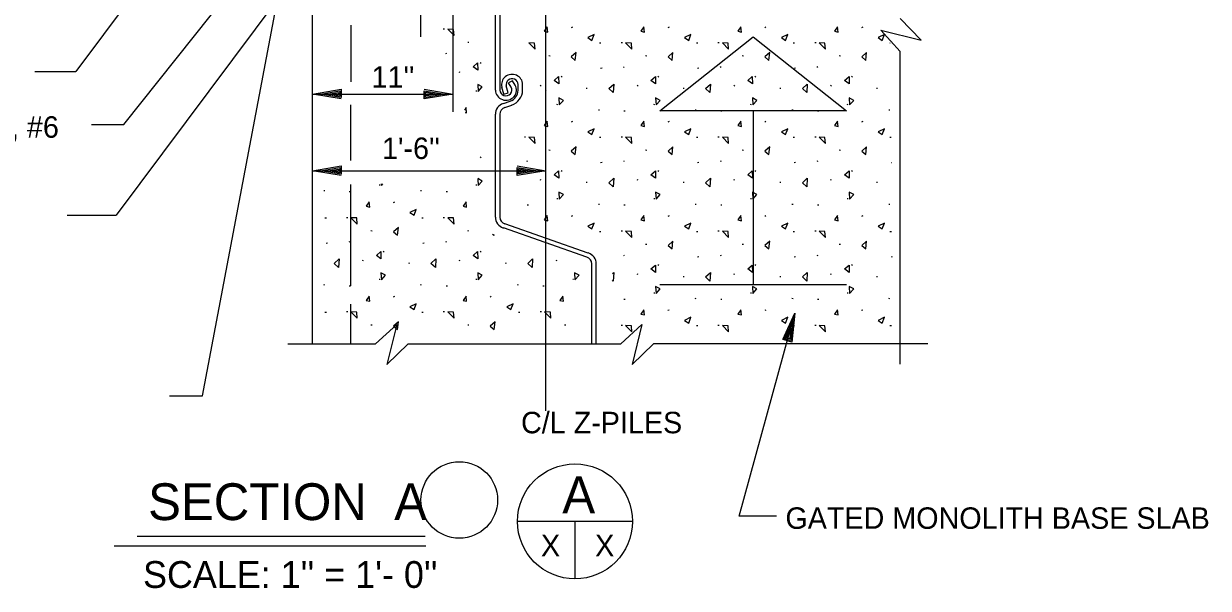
# Model space of a CAD drawing. Extents: x 22369.6 to 22428.3, y 22369.6 to 22415.
# Drawn here: x 22399.65 to 22409.95, y 22392.13 to 22397.04 of the extents above; entities that cross this region are included whole.
import ezdxf

# ---------------------------------------------------------------- set-up
doc = ezdxf.new("R2010")
doc.units = 0
for name, color, linetype in [('Level 1', 7, 'Continuous'), ('Level 10', 7, 'Continuous'), ('Level 2', 7, 'Continuous'), ('Level 3', 7, 'Continuous'), ('Level 4', 7, 'Continuous'), ('Level 44', 7, 'Continuous'), ('Level 7', 7, 'Continuous')]:
    doc.layers.add(name, color=color, linetype=linetype)

msp = doc.modelspace()

# ---------------------------------------------------------------- linework, layer by layer
at = {"layer": 'Level 1'}
for p, q in [((22403.103, 22396.931), (22403.103, 22400.124)), ((22404.188, 22393.677), (22404.188, 22399.363)), ((22403.381, 22399.057), (22403.381, 22396.277)), ((22402.977, 22398.76), (22400.451, 22395.38)), ((22401.272, 22398.196), (22400.102, 22396.63)), ((22407.451, 22396.902), (22407.27, 22397.089)), ((22407.27, 22396.804), (22407.102, 22396.988)), ((22407.102, 22396.988), (22407.451, 22396.902)), ((22407.27, 22394.082), (22407.27, 22396.804)), ((22399.745, 22396.63), (22400.102, 22396.63)), ((22402.159, 22396.432), (22403.381, 22396.432)), ((22404.19, 22396.466), (22404.19, 22396.466)), ((22404.194, 22396.466), (22404.194, 22396.466)), ((22402.159, 22395.766), (22404.188, 22395.766)), ((22400.025, 22395.38), (22400.451, 22395.38)), ((22402.708, 22394.26), (22402.892, 22394.429)), ((22402.892, 22394.429), (22402.806, 22394.079)), ((22404.84, 22394.26), (22405.024, 22394.429)), ((22405.024, 22394.429), (22404.938, 22394.079)), ((22401.945, 22394.26), (22402.708, 22394.26)), ((22402.806, 22394.079), (22402.992, 22394.26)), ((22402.992, 22394.26), (22404.84, 22394.26)), ((22404.938, 22394.079), (22405.125, 22394.26)), ((22407.51, 22394.26), (22405.125, 22394.26))]:
    msp.add_line(p, q, dxfattribs=at)
for points in [[(22400.916, 22393.807), (22401.203, 22393.807), (22402.11, 22398.602)], [(22400.238, 22396.169), (22400.519, 22396.169), (22401.736, 22397.698)], [(22406.194, 22392.76), (22405.871, 22392.76), (22406.355, 22394.528)]]:
    msp.add_lwpolyline(points, dxfattribs=at)
at = {"layer": 'Level 10'}
for p, q in [((22402.492, 22397.032), (22402.492, 22396.538)), ((22402.492, 22395.855), (22402.492, 22396.338)), ((22406.803, 22396.286), (22405.181, 22396.286)), ((22405.992, 22396.286), (22405.992, 22394.772)), ((22402.492, 22394.766), (22402.492, 22395.645)), ((22406.803, 22394.772), (22405.181, 22394.772)), ((22402.492, 22394.26), (22402.492, 22394.604)), ((22400.634, 22392.586), (22403.138, 22392.586)), ((22400.434, 22392.503), (22403.144, 22392.503))]:
    msp.add_line(p, q, dxfattribs=at)
msp.add_lwpolyline([(22405.181, 22396.286), (22405.992, 22396.931), (22406.803, 22396.286)], close=True, dxfattribs=at)
at = {"layer": 'Level 2'}
for p, q in [((22403.751, 22396.467), (22403.751, 22397.362)), ((22403.79, 22396.467), (22403.79, 22397.362)), ((22403.899, 22396.549), (22403.865, 22396.53)), ((22403.922, 22396.511), (22403.899, 22396.549)), ((22402.159, 22396.432), (22402.159, 22396.432)), ((22402.228, 22396.432), (22402.228, 22396.432)), ((22403.311, 22396.432), (22403.311, 22396.432)), ((22403.381, 22396.432), (22403.381, 22396.432)), ((22403.823, 22396.433), (22403.806, 22396.493)), ((22403.823, 22396.433), (22403.861, 22396.442)), ((22403.861, 22396.442), (22403.844, 22396.503)), ((22403.888, 22396.492), (22403.865, 22396.53)), ((22403.947, 22396.466), (22403.947, 22396.516)), ((22403.986, 22396.466), (22403.986, 22396.516)), ((22404.188, 22396.467), (22404.188, 22396.467)), ((22403.82, 22396.351), (22403.878, 22396.372)), ((22403.833, 22396.316), (22403.892, 22396.336)), ((22403.751, 22395.362), (22403.751, 22396.257)), ((22403.79, 22395.362), (22403.79, 22396.257)), ((22402.159, 22395.766), (22402.159, 22395.766)), ((22402.228, 22395.766), (22402.228, 22395.766)), ((22404.119, 22395.766), (22404.119, 22395.766)), ((22404.188, 22395.766), (22404.188, 22395.766)), ((22404.558, 22395.05), (22403.833, 22395.303)), ((22404.545, 22395.015), (22403.82, 22395.268)), ((22404.588, 22394.26), (22404.588, 22394.956)), ((22404.627, 22394.26), (22404.627, 22394.956)), ((22406.355, 22394.528), (22406.355, 22394.528)), ((22406.337, 22394.461), (22406.337, 22394.461))]:
    msp.add_line(p, q, dxfattribs=at)
for points in [[(22402.408, 22396.391), (22402.159, 22396.432), (22402.408, 22396.474), (22402.408, 22396.403), (22402.228, 22396.432), (22402.397, 22396.46), (22402.397, 22396.415), (22402.295, 22396.432), (22402.387, 22396.447), (22402.387, 22396.428), (22402.364, 22396.432)], [(22403.131, 22396.474), (22403.381, 22396.432), (22403.131, 22396.391), (22403.131, 22396.462), (22403.311, 22396.432), (22403.142, 22396.404), (22403.142, 22396.45), (22403.245, 22396.432), (22403.153, 22396.418), (22403.153, 22396.436), (22403.175, 22396.432)], [(22402.408, 22395.724), (22402.159, 22395.766), (22402.408, 22395.807), (22402.408, 22395.736), (22402.228, 22395.766), (22402.397, 22395.794), (22402.397, 22395.748), (22402.295, 22395.766), (22402.387, 22395.78), (22402.387, 22395.762), (22402.364, 22395.766)], [(22403.939, 22395.807), (22404.188, 22395.766), (22403.939, 22395.724), (22403.939, 22395.795), (22404.119, 22395.766), (22403.95, 22395.738), (22403.95, 22395.783), (22404.052, 22395.766), (22403.96, 22395.751), (22403.96, 22395.77), (22403.983, 22395.766)], [(22406.25, 22394.298), (22406.355, 22394.528), (22406.329, 22394.276), (22406.261, 22394.295), (22406.337, 22394.461), (22406.319, 22394.29), (22406.276, 22394.302), (22406.319, 22394.396), (22406.309, 22394.304), (22406.291, 22394.309), (22406.301, 22394.33)]]:
    msp.add_lwpolyline(points, dxfattribs=at)
for centre, major_axis, start_param, end_param in [((22403.895, 22396.516), (0.0916, 0), 0, 3.403392), ((22403.895, 22396.516), (0.0523, 0), 0, 3.403392), ((22403.842, 22396.467), (-0.0916, 0), 0, 3.665191), ((22403.842, 22396.467), (-0.0523, 0), 0, 3.665191), ((22403.842, 22396.466), (0.105, 0), 5.061528, 6.283185), ((22403.842, 22396.466), (0.144, 0), 5.061528, 6.283185), ((22403.855, 22396.257), (0.105, 0), 1.919936, 3.141593), ((22403.855, 22396.257), (0.0654, 0), 1.919936, 3.141593), ((22403.855, 22395.362), (0.105, 0), 3.141593, 4.363142), ((22403.855, 22395.362), (0.0654, 0), 3.141593, 4.363142), ((22404.522, 22394.956), (0.0654, 0), 0, 1.22155), ((22404.522, 22394.956), (0.105, 0), 0, 1.22155)]:
    msp.add_ellipse(centre, major_axis=major_axis, ratio=0.957796, start_param=start_param, end_param=end_param, dxfattribs=at)
at = {"layer": 'Level 3'}
for centre, radius in [((22403.436, 22392.902), 0.333), ((22404.442, 22392.716), 0.5)]:
    msp.add_circle(centre, radius, dxfattribs=at)
at = {"layer": 'Level 4'}
msp.add_line((22404.19, 22394.06), (22404.19, 22394.06), dxfattribs=at)
at = {"layer": 'Level 44'}
for p, q in [((22403.308, 22396.997), (22403.297, 22396.997)), ((22404.419, 22397.013), (22404.409, 22397.008)), ((22405.26, 22397.013), (22405.25, 22397.008)), ((22406.102, 22397.013), (22406.092, 22397.008)), ((22406.944, 22397.013), (22406.934, 22397.008)), ((22403.52, 22396.88), (22403.509, 22396.882)), ((22404.668, 22396.875), (22404.656, 22396.875)), ((22404.854, 22396.879), (22404.844, 22396.879)), ((22405.509, 22396.875), (22405.498, 22396.875)), ((22405.696, 22396.879), (22405.685, 22396.879)), ((22406.351, 22396.875), (22406.34, 22396.875)), ((22406.538, 22396.879), (22406.527, 22396.879)), ((22407.184, 22396.875), (22407.181, 22396.875)), ((22403.324, 22396.786), (22403.316, 22396.783)), ((22404.225, 22396.763), (22404.214, 22396.764)), ((22405.066, 22396.763), (22405.056, 22396.764)), ((22405.908, 22396.763), (22405.897, 22396.764)), ((22406.75, 22396.763), (22406.739, 22396.764)), ((22403.626, 22396.698), (22403.617, 22396.703)), ((22404.677, 22396.657), (22404.665, 22396.654)), ((22404.871, 22396.668), (22404.863, 22396.665)), ((22405.518, 22396.657), (22405.507, 22396.654)), ((22405.712, 22396.668), (22405.704, 22396.665)), ((22406.36, 22396.657), (22406.349, 22396.654)), ((22406.554, 22396.668), (22406.546, 22396.665)), ((22403.445, 22396.62), (22403.436, 22396.624)), ((22404.331, 22396.58), (22404.321, 22396.585)), ((22405.172, 22396.58), (22405.163, 22396.585)), ((22406.014, 22396.58), (22406.005, 22396.585)), ((22406.856, 22396.58), (22406.846, 22396.585)), ((22403.589, 22396.458), (22403.58, 22396.459)), ((22404.149, 22396.502), (22404.14, 22396.506)), ((22404.549, 22396.482), (22404.54, 22396.481)), ((22404.991, 22396.502), (22404.982, 22396.506)), ((22405.391, 22396.482), (22405.382, 22396.481)), ((22405.833, 22396.502), (22405.824, 22396.506)), ((22406.232, 22396.482), (22406.223, 22396.481)), ((22406.674, 22396.502), (22406.665, 22396.506)), ((22407.074, 22396.482), (22407.065, 22396.481)), ((22404.293, 22396.34), (22404.285, 22396.341)), ((22405.135, 22396.34), (22405.127, 22396.341)), ((22405.977, 22396.34), (22405.968, 22396.341)), ((22406.818, 22396.34), (22406.81, 22396.341)), ((22404.654, 22396.292), (22404.646, 22396.293)), ((22404.879, 22396.285), (22404.867, 22396.285)), ((22405.496, 22396.292), (22405.488, 22396.293)), ((22405.72, 22396.285), (22405.709, 22396.285)), ((22406.338, 22396.292), (22406.329, 22396.293)), ((22406.562, 22396.285), (22406.551, 22396.285)), ((22407.179, 22396.292), (22407.171, 22396.293)), ((22404.419, 22396.194), (22404.409, 22396.189)), ((22405.26, 22396.194), (22405.25, 22396.189)), ((22406.102, 22396.194), (22406.092, 22396.189)), ((22406.944, 22396.194), (22406.934, 22396.189)), ((22404.013, 22396.059), (22404.003, 22396.059)), ((22404.668, 22396.055), (22404.656, 22396.055)), ((22404.854, 22396.059), (22404.844, 22396.059)), ((22405.509, 22396.055), (22405.498, 22396.055)), ((22405.696, 22396.059), (22405.685, 22396.059)), ((22406.351, 22396.055), (22406.34, 22396.055)), ((22406.538, 22396.059), (22406.527, 22396.059)), ((22407.191, 22396.055), (22407.181, 22396.055)), ((22404.225, 22395.943), (22404.214, 22395.945)), ((22405.066, 22395.943), (22405.056, 22395.945)), ((22405.908, 22395.943), (22405.897, 22395.945)), ((22406.75, 22395.943), (22406.739, 22395.945)), ((22403.626, 22395.878), (22403.617, 22395.884)), ((22404.029, 22395.848), (22404.021, 22395.845)), ((22404.677, 22395.837), (22404.665, 22395.834)), ((22404.871, 22395.848), (22404.863, 22395.845)), ((22405.518, 22395.837), (22405.507, 22395.834)), ((22405.712, 22395.848), (22405.704, 22395.845)), ((22406.36, 22395.837), (22406.349, 22395.834)), ((22406.554, 22395.848), (22406.546, 22395.845)), ((22407.193, 22395.835), (22407.19, 22395.834)), ((22404.331, 22395.76), (22404.321, 22395.766)), ((22405.172, 22395.76), (22405.163, 22395.766)), ((22406.014, 22395.76), (22406.005, 22395.766)), ((22406.856, 22395.76), (22406.846, 22395.766)), ((22402.747, 22395.639), (22402.739, 22395.639)), ((22403.589, 22395.639), (22403.58, 22395.639)), ((22404.149, 22395.683), (22404.14, 22395.687)), ((22404.549, 22395.663), (22404.54, 22395.662)), ((22404.991, 22395.683), (22404.982, 22395.687)), ((22405.391, 22395.663), (22405.382, 22395.662)), ((22405.833, 22395.683), (22405.824, 22395.687)), ((22406.232, 22395.663), (22406.223, 22395.662)), ((22406.674, 22395.683), (22406.665, 22395.687)), ((22407.074, 22395.663), (22407.065, 22395.662)), ((22402.266, 22395.59), (22402.258, 22395.591)), ((22402.49, 22395.583), (22402.479, 22395.583)), ((22403.108, 22395.59), (22403.1, 22395.591)), ((22403.332, 22395.583), (22403.321, 22395.583)), ((22404.293, 22395.521), (22404.285, 22395.521)), ((22405.135, 22395.521), (22405.127, 22395.521)), ((22405.977, 22395.521), (22405.968, 22395.521)), ((22406.818, 22395.521), (22406.81, 22395.521)), ((22402.872, 22395.492), (22402.862, 22395.487)), ((22404.037, 22395.465), (22404.026, 22395.465)), ((22404.654, 22395.472), (22404.646, 22395.473)), ((22404.879, 22395.465), (22404.867, 22395.465)), ((22405.496, 22395.472), (22405.488, 22395.473)), ((22405.72, 22395.465), (22405.709, 22395.465)), ((22406.338, 22395.472), (22406.329, 22395.473)), ((22406.562, 22395.465), (22406.551, 22395.465)), ((22407.179, 22395.472), (22407.171, 22395.473)), ((22402.28, 22395.353), (22402.268, 22395.353)), ((22402.466, 22395.357), (22402.456, 22395.357)), ((22403.121, 22395.353), (22403.11, 22395.353)), ((22403.308, 22395.357), (22403.297, 22395.357)), ((22404.419, 22395.374), (22404.409, 22395.369)), ((22405.26, 22395.374), (22405.25, 22395.369)), ((22406.102, 22395.374), (22406.092, 22395.369)), ((22406.944, 22395.374), (22406.934, 22395.369)), ((22402.678, 22395.241), (22402.668, 22395.243)), ((22403.52, 22395.241), (22403.509, 22395.243)), ((22404.668, 22395.235), (22404.656, 22395.235)), ((22404.854, 22395.239), (22404.844, 22395.239)), ((22405.509, 22395.235), (22405.498, 22395.235)), ((22405.696, 22395.239), (22405.685, 22395.239)), ((22406.351, 22395.235), (22406.34, 22395.235)), ((22406.538, 22395.239), (22406.527, 22395.239)), ((22407.193, 22395.235), (22407.181, 22395.235)), ((22402.289, 22395.135), (22402.277, 22395.132)), ((22402.483, 22395.147), (22402.475, 22395.143)), ((22403.13, 22395.135), (22403.119, 22395.132)), ((22403.324, 22395.147), (22403.316, 22395.143)), ((22405.066, 22395.123), (22405.056, 22395.125)), ((22405.908, 22395.123), (22405.897, 22395.125)), ((22406.75, 22395.123), (22406.739, 22395.125)), ((22402.784, 22395.058), (22402.775, 22395.064)), ((22403.626, 22395.058), (22403.617, 22395.064)), ((22404.871, 22395.029), (22404.863, 22395.025)), ((22405.518, 22395.017), (22405.507, 22395.014)), ((22405.712, 22395.029), (22405.704, 22395.025)), ((22406.36, 22395.017), (22406.349, 22395.014)), ((22406.554, 22395.029), (22406.546, 22395.025)), ((22407.2, 22395.017), (22407.19, 22395.014)), ((22402.603, 22394.981), (22402.594, 22394.985)), ((22403.003, 22394.961), (22402.994, 22394.96)), ((22403.445, 22394.981), (22403.436, 22394.985)), ((22403.844, 22394.961), (22403.835, 22394.96)), ((22404.286, 22394.981), (22404.277, 22394.985)), ((22405.172, 22394.94), (22405.163, 22394.946)), ((22406.014, 22394.94), (22406.005, 22394.946)), ((22406.856, 22394.94), (22406.846, 22394.946)), ((22402.747, 22394.819), (22402.739, 22394.819)), ((22403.589, 22394.819), (22403.58, 22394.819)), ((22404.43, 22394.819), (22404.422, 22394.819)), ((22404.991, 22394.863), (22404.982, 22394.867)), ((22405.391, 22394.843), (22405.382, 22394.842)), ((22405.833, 22394.863), (22405.824, 22394.867)), ((22406.232, 22394.843), (22406.223, 22394.842)), ((22406.674, 22394.863), (22406.665, 22394.867)), ((22407.074, 22394.843), (22407.065, 22394.842)), ((22402.266, 22394.77), (22402.258, 22394.772)), ((22402.49, 22394.763), (22402.479, 22394.763)), ((22403.108, 22394.77), (22403.1, 22394.772)), ((22403.332, 22394.763), (22403.321, 22394.763)), ((22403.95, 22394.77), (22403.941, 22394.772)), ((22404.174, 22394.763), (22404.163, 22394.763)), ((22405.135, 22394.701), (22405.127, 22394.701)), ((22405.977, 22394.701), (22405.968, 22394.701)), ((22406.818, 22394.701), (22406.81, 22394.701)), ((22402.872, 22394.672), (22402.862, 22394.667)), ((22403.714, 22394.672), (22403.704, 22394.667)), ((22404.879, 22394.645), (22404.867, 22394.645)), ((22405.496, 22394.652), (22405.488, 22394.654)), ((22405.72, 22394.645), (22405.709, 22394.645)), ((22406.338, 22394.652), (22406.329, 22394.654)), ((22406.562, 22394.645), (22406.551, 22394.645)), ((22407.179, 22394.652), (22407.171, 22394.654)), ((22402.28, 22394.534), (22402.268, 22394.534)), ((22402.466, 22394.538), (22402.456, 22394.538)), ((22403.121, 22394.534), (22403.11, 22394.534)), ((22403.308, 22394.538), (22403.297, 22394.538)), ((22403.963, 22394.534), (22403.952, 22394.534)), ((22404.15, 22394.538), (22404.139, 22394.538)), ((22405.26, 22394.554), (22405.25, 22394.549)), ((22406.102, 22394.554), (22406.092, 22394.549)), ((22406.944, 22394.554), (22406.934, 22394.549)), ((22402.678, 22394.421), (22402.668, 22394.423)), ((22403.52, 22394.421), (22403.509, 22394.423)), ((22404.362, 22394.421), (22404.351, 22394.423)), ((22404.854, 22394.42), (22404.844, 22394.42)), ((22405.509, 22394.416), (22405.498, 22394.416)), ((22405.696, 22394.42), (22405.685, 22394.42)), ((22406.351, 22394.416), (22406.34, 22394.416)), ((22406.538, 22394.42), (22406.527, 22394.42)), ((22407.193, 22394.416), (22407.181, 22394.416))]:
    msp.add_line(p, q, dxfattribs=at)
for points in [[(22403.386, 22396.994), (22403.336, 22396.997), (22403.39, 22396.942)], [(22404.205, 22396.971), (22404.199, 22397.017), (22404.174, 22396.979)], [(22404.589, 22396.899), (22404.609, 22396.95), (22404.554, 22396.924)], [(22405.047, 22396.971), (22405.041, 22397.017), (22405.015, 22396.979)], [(22405.431, 22396.899), (22405.45, 22396.95), (22405.395, 22396.924)], [(22405.889, 22396.971), (22405.883, 22397.017), (22405.857, 22396.979)], [(22406.272, 22396.899), (22406.292, 22396.95), (22406.237, 22396.924)], [(22406.73, 22396.971), (22406.724, 22397.017), (22406.699, 22396.979)], [(22407.114, 22396.899), (22407.134, 22396.95), (22407.079, 22396.924)], [(22404.091, 22396.876), (22404.041, 22396.879), (22404.095, 22396.824)], [(22404.932, 22396.876), (22404.882, 22396.879), (22404.937, 22396.824)], [(22405.774, 22396.876), (22405.724, 22396.879), (22405.778, 22396.824)], [(22406.616, 22396.876), (22406.566, 22396.879), (22406.62, 22396.824)], [(22404.452, 22396.793), (22404.41, 22396.755), (22404.445, 22396.725)], [(22405.294, 22396.793), (22405.251, 22396.755), (22405.287, 22396.725)], [(22406.136, 22396.793), (22406.093, 22396.755), (22406.128, 22396.725)], [(22406.977, 22396.793), (22406.935, 22396.755), (22406.97, 22396.725)], [(22403.596, 22396.639), (22403.556, 22396.669), (22403.595, 22396.703)], [(22404.301, 22396.521), (22404.261, 22396.551), (22404.3, 22396.585)], [(22405.143, 22396.521), (22405.103, 22396.551), (22405.141, 22396.585)], [(22405.985, 22396.521), (22405.945, 22396.551), (22405.983, 22396.585)], [(22406.826, 22396.521), (22406.786, 22396.551), (22406.825, 22396.585)], [(22403.601, 22396.455), (22403.636, 22396.495), (22403.596, 22396.517)], [(22404.774, 22396.446), (22404.736, 22396.481), (22404.779, 22396.519)], [(22405.616, 22396.446), (22405.577, 22396.481), (22405.62, 22396.519)], [(22406.458, 22396.446), (22406.419, 22396.481), (22406.462, 22396.519)], [(22404.305, 22396.338), (22404.341, 22396.378), (22404.301, 22396.399)], [(22405.147, 22396.338), (22405.183, 22396.378), (22405.143, 22396.399)], [(22405.989, 22396.338), (22406.024, 22396.378), (22405.985, 22396.399)], [(22406.83, 22396.338), (22406.866, 22396.378), (22406.826, 22396.399)], [(22404.205, 22396.151), (22404.199, 22396.197), (22404.174, 22396.159)], [(22404.589, 22396.08), (22404.609, 22396.131), (22404.554, 22396.104)], [(22405.047, 22396.151), (22405.041, 22396.197), (22405.015, 22396.159)], [(22405.431, 22396.08), (22405.45, 22396.131), (22405.395, 22396.104)], [(22405.889, 22396.151), (22405.883, 22396.197), (22405.857, 22396.159)], [(22406.272, 22396.08), (22406.292, 22396.131), (22406.237, 22396.104)], [(22406.73, 22396.151), (22406.724, 22396.197), (22406.699, 22396.159)], [(22407.114, 22396.08), (22407.134, 22396.131), (22407.079, 22396.104)], [(22404.091, 22396.056), (22404.041, 22396.059), (22404.095, 22396.004)], [(22404.932, 22396.056), (22404.882, 22396.059), (22404.937, 22396.004)], [(22405.774, 22396.056), (22405.724, 22396.059), (22405.778, 22396.004)], [(22406.616, 22396.056), (22406.566, 22396.059), (22406.62, 22396.004)], [(22404.452, 22395.973), (22404.41, 22395.935), (22404.445, 22395.906)], [(22405.294, 22395.973), (22405.251, 22395.935), (22405.287, 22395.906)], [(22406.136, 22395.973), (22406.093, 22395.935), (22406.128, 22395.906)], [(22406.977, 22395.973), (22406.935, 22395.935), (22406.97, 22395.906)], [(22404.301, 22395.701), (22404.261, 22395.731), (22404.3, 22395.765)], [(22405.143, 22395.701), (22405.103, 22395.731), (22405.141, 22395.765)], [(22405.985, 22395.701), (22405.945, 22395.731), (22405.983, 22395.765)], [(22406.826, 22395.701), (22406.786, 22395.731), (22406.825, 22395.765)], [(22404.774, 22395.626), (22404.736, 22395.661), (22404.779, 22395.7)], [(22405.616, 22395.626), (22405.577, 22395.661), (22405.62, 22395.7)], [(22406.458, 22395.626), (22406.419, 22395.661), (22406.462, 22395.7)], [(22404.305, 22395.518), (22404.341, 22395.558), (22404.301, 22395.579)], [(22405.147, 22395.518), (22405.183, 22395.558), (22405.143, 22395.579)], [(22405.989, 22395.518), (22406.024, 22395.558), (22405.985, 22395.579)], [(22406.83, 22395.518), (22406.866, 22395.558), (22406.826, 22395.579)], [(22402.659, 22395.449), (22402.653, 22395.495), (22402.627, 22395.457)], [(22403.043, 22395.378), (22403.062, 22395.429), (22403.007, 22395.402)], [(22403.5, 22395.449), (22403.495, 22395.495), (22403.469, 22395.457)], [(22402.544, 22395.355), (22402.494, 22395.357), (22402.549, 22395.302)], [(22403.386, 22395.355), (22403.336, 22395.357), (22403.39, 22395.302)], [(22404.205, 22395.331), (22404.199, 22395.377), (22404.174, 22395.339)], [(22404.589, 22395.26), (22404.609, 22395.311), (22404.554, 22395.284)], [(22405.047, 22395.331), (22405.041, 22395.377), (22405.015, 22395.339)], [(22405.431, 22395.26), (22405.45, 22395.311), (22405.395, 22395.284)], [(22405.889, 22395.331), (22405.883, 22395.377), (22405.857, 22395.339)], [(22406.272, 22395.26), (22406.292, 22395.311), (22406.237, 22395.284)], [(22406.73, 22395.331), (22406.724, 22395.377), (22406.699, 22395.339)], [(22407.114, 22395.26), (22407.134, 22395.311), (22407.079, 22395.284)], [(22402.906, 22395.271), (22402.863, 22395.234), (22402.899, 22395.204)], [(22404.932, 22395.237), (22404.882, 22395.239), (22404.937, 22395.184)], [(22405.774, 22395.237), (22405.724, 22395.239), (22405.778, 22395.184)], [(22406.616, 22395.237), (22406.566, 22395.239), (22406.62, 22395.184)], [(22405.294, 22395.153), (22405.251, 22395.116), (22405.287, 22395.086)], [(22406.136, 22395.153), (22406.093, 22395.116), (22406.128, 22395.086)], [(22406.977, 22395.153), (22406.935, 22395.116), (22406.97, 22395.086)], [(22402.386, 22394.924), (22402.348, 22394.96), (22402.39, 22394.998)], [(22402.755, 22394.999), (22402.715, 22395.029), (22402.753, 22395.063)], [(22403.228, 22394.924), (22403.189, 22394.96), (22403.232, 22394.998)], [(22403.596, 22394.999), (22403.556, 22395.029), (22403.595, 22395.063)], [(22404.07, 22394.924), (22404.031, 22394.96), (22404.074, 22394.998)], [(22405.143, 22394.881), (22405.103, 22394.911), (22405.141, 22394.945)], [(22405.985, 22394.881), (22405.945, 22394.911), (22405.983, 22394.945)], [(22406.826, 22394.881), (22406.786, 22394.911), (22406.825, 22394.945)], [(22402.759, 22394.816), (22402.795, 22394.856), (22402.755, 22394.877)], [(22403.601, 22394.816), (22403.636, 22394.856), (22403.596, 22394.877)], [(22404.442, 22394.816), (22404.478, 22394.856), (22404.438, 22394.877)], [(22405.616, 22394.806), (22405.577, 22394.842), (22405.62, 22394.88)], [(22406.458, 22394.806), (22406.419, 22394.842), (22406.462, 22394.88)], [(22405.147, 22394.698), (22405.183, 22394.738), (22405.143, 22394.759)], [(22405.989, 22394.698), (22406.024, 22394.738), (22405.985, 22394.759)], [(22406.83, 22394.698), (22406.866, 22394.738), (22406.826, 22394.759)], [(22402.659, 22394.63), (22402.653, 22394.675), (22402.627, 22394.637)], [(22403.043, 22394.558), (22403.062, 22394.609), (22403.007, 22394.582)], [(22403.5, 22394.63), (22403.495, 22394.675), (22403.469, 22394.637)], [(22403.884, 22394.558), (22403.904, 22394.609), (22403.849, 22394.582)], [(22404.342, 22394.63), (22404.336, 22394.675), (22404.311, 22394.637)], [(22402.544, 22394.535), (22402.494, 22394.538), (22402.549, 22394.482)], [(22403.386, 22394.535), (22403.336, 22394.538), (22403.39, 22394.482)], [(22404.228, 22394.535), (22404.178, 22394.538), (22404.232, 22394.482)], [(22405.047, 22394.512), (22405.041, 22394.557), (22405.015, 22394.519)], [(22405.431, 22394.44), (22405.45, 22394.491), (22405.395, 22394.464)], [(22405.889, 22394.512), (22405.883, 22394.557), (22405.857, 22394.519)], [(22406.272, 22394.44), (22406.292, 22394.491), (22406.237, 22394.464)], [(22406.73, 22394.512), (22406.724, 22394.557), (22406.699, 22394.519)], [(22407.114, 22394.44), (22407.134, 22394.491), (22407.079, 22394.464)], [(22402.906, 22394.451), (22402.863, 22394.414), (22402.899, 22394.384)], [(22403.748, 22394.451), (22403.705, 22394.414), (22403.74, 22394.384)], [(22404.932, 22394.417), (22404.882, 22394.42), (22404.937, 22394.364)], [(22405.774, 22394.417), (22405.724, 22394.42), (22405.778, 22394.364)], [(22406.616, 22394.417), (22406.566, 22394.42), (22406.62, 22394.364)]]:
    msp.add_lwpolyline(points, close=True, dxfattribs=at)
for points in [[(22403.5, 22396.269), (22403.495, 22396.315), (22403.48, 22396.293)], [(22403.488, 22396.272), (22403.5, 22396.269)], [(22402.758, 22395.651), (22402.759, 22395.636)], [(22402.759, 22395.636), (22402.772, 22395.651)], [(22403.601, 22395.636), (22403.636, 22395.676), (22403.597, 22395.697)], [(22403.597, 22395.692), (22403.601, 22395.636)], [(22403.726, 22395.215), (22403.74, 22395.204), (22403.741, 22395.21)], [(22404.774, 22394.806), (22404.767, 22394.813)], [(22404.769, 22394.871), (22404.779, 22394.88), (22404.774, 22394.806)]]:
    msp.add_lwpolyline(points, dxfattribs=at)
at = {"layer": 'Level 7'}
for p, q in [((22402.159, 22394.26), (22402.159, 22399.93)), ((22404.942, 22392.716), (22403.942, 22392.716)), ((22404.442, 22392.716), (22404.442, 22392.216))]:
    msp.add_line(p, q, dxfattribs=at)

# ---------------------------------------------------------------- texts
at = {"layer": 'Level 3'}
for s, p in [('SECTION  A', (22400.73, 22392.727)), ('A', (22404.332, 22392.787))]:
    msp.add_text(s, height=0.32, dxfattribs=at).set_placement(p)
at = {"layer": 'Level 4'}
for s, height, p in [("11''", 0.1867, (22402.673, 22396.488)), ('2, #6', 0.1867, (22399.399, 22396.053)), ("1'-6''", 0.1867, (22402.764, 22395.868)), ('C/L Z-PILES', 0.18669, (22403.973, 22393.482)), ('GATED MONOLITH BASE SLAB', 0.18669, (22406.272, 22392.651))]:
    msp.add_text(s, height=height, dxfattribs=at).set_placement(p)
at = {"layer": 'Level 7'}
for s, height, p in [('X', 0.187, (22404.146, 22392.412)), ('X', 0.187, (22404.617, 22392.412)), ("SCALE: 1'' = 1'- 0''", 0.23333, (22400.686, 22392.137))]:
    msp.add_text(s, height=height, dxfattribs=at).set_placement(p)

doc.saveas('drawing.dxf')
